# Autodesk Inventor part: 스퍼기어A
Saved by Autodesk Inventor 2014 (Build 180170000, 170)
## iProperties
Created: 2024-05
Part Number: 스퍼기어A
Material: 일반
Document SubType Name: Modeling
Designer: dg
Density: 1 g/cm^3
Appearance: 기본값
Author: dg
Author: jhkim
Creation Date: 2024-05-10
Sending System: Autodesk Inventor 2025
Preprocessor: ST-DEVELOPER v20
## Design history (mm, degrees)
node "스퍼기어A1"
node "솔리드1"
node "기준1"
